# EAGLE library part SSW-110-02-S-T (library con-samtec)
THROUGH-HOLE .025" SQ POST SOCKET Source: Samtec SSW.pdf
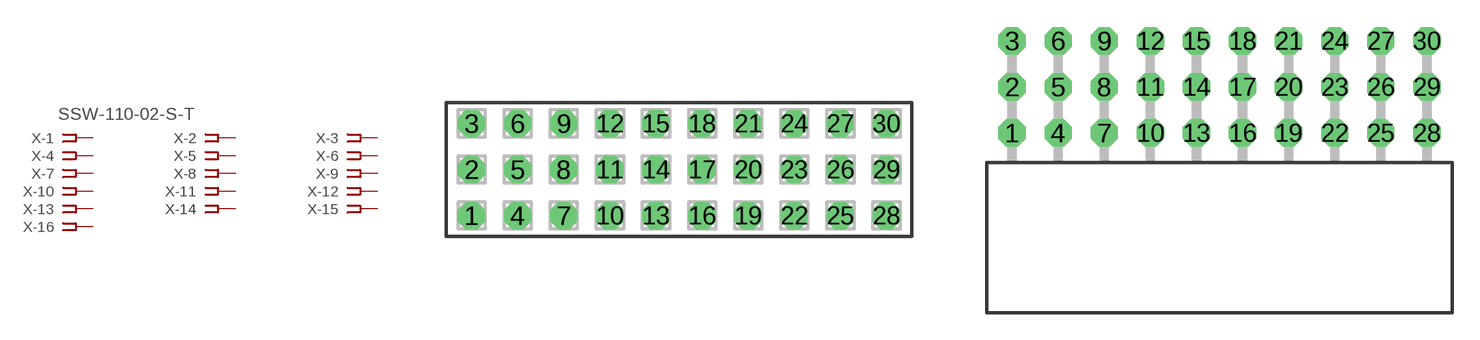
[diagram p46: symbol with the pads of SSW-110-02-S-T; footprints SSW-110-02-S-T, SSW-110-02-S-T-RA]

Designator prefix X; gates -1=FPINV -2=FPIN -3=FPIN -4=FPIN -5=FPIN -6=FPIN -7=FPIN -8=FPIN -9=FPIN -10=FPIN -11=FPIN -12=FPIN -13=FPIN -14=FPIN -15=FPIN -16=FPIN -17=FPIN -18=FPIN -19=FPIN -20=FPIN -21=FPIN -22=FPIN -23=FPIN -24=FPIN -25=FPIN -26=FPIN -27=FPIN -28=FPIN -29=FPIN -30=FPIN

## SSW-110-02-S-T (MPN: SSW-110-02-S-T; OC_FARNELL: unknown; OC_NEWARK: 82P5236)  [SSW-110-02-S-T]
1  -1:1  pas
2  -2:1  pas
3  -3:1  pas
4  -4:1  pas
5  -5:1  pas
6  -6:1  pas
7  -7:1  pas
8  -8:1  pas
9  -9:1  pas
10  -10:1  pas
11  -11:1  pas
12  -12:1  pas
13  -13:1  pas
14  -14:1  pas
15  -15:1  pas
16  -16:1  pas
17  -17:1  pas
18  -18:1  pas
19  -19:1  pas
20  -20:1  pas
21  -21:1  pas
22  -22:1  pas
23  -23:1  pas
24  -24:1  pas
25  -25:1  pas
26  -26:1  pas
27  -27:1  pas
28  -28:1  pas
29  -29:1  pas
30  -30:1  pas

## SSW-110-02-S-TRA (MPN: SSW-110-02-S-T-RA; OC_FARNELL: unknown; OC_NEWARK: 82P5237)  [SSW-110-02-S-T-RA]
Pads as for SSW-110-02-S-T

## Footprint SSW-110-02-S-T (pad centres in mm)
THROUGH-HOLE .025" SQ POST SOCKET Source: Samtec SSW.pdf
drill 1 pad 1.5 octagon: 1 -11.43,-2.54; 2 -11.43,0; 3 -11.43,2.54; 4 -8.89,-2.54; 5 -8.89,0; 6 -8.89,2.54; 7 -6.35,-2.54; 8 -6.35,0; 9 -6.35,2.54; 10 -3.81,-2.54; 11 -3.81,0; 12 -3.81,2.54; 13 -1.27,-2.54; 14 -1.27,0; 15 -1.27,2.54; 16 1.27,-2.54; 17 1.27,0; 18 1.27,2.54; 19 3.81,-2.54; 20 3.81,0; 21 3.81,2.54; 22 6.35,-2.54; 23 6.35,0; 24 6.35,2.54; 25 8.89,-2.54; 26 8.89,0; 27 8.89,2.54; 28 11.43,-2.54; 29 11.43,0; 30 11.43,2.54

## Footprint SSW-110-02-S-T-RA (pad centres in mm)
THROUGH-HOLE .025" SQ POST SOCKET Source: Samtec SSW.pdf
drill 1 pad 1.5 octagon: 1 -11.43,1.524; 2 -11.43,4.064; 3 -11.43,6.604; 4 -8.89,1.524; 5 -8.89,4.064; 6 -8.89,6.604; 7 -6.35,1.524; 8 -6.35,4.064; 9 -6.35,6.604; 10 -3.81,1.524; 11 -3.81,4.064; 12 -3.81,6.604; 13 -1.27,1.524; 14 -1.27,4.064; 15 -1.27,6.604; 16 1.27,1.524; 17 1.27,4.064; 18 1.27,6.604; 19 3.81,1.524; 20 3.81,4.064; 21 3.81,6.604; 22 6.35,1.524; 23 6.35,4.064; 24 6.35,6.604; 25 8.89,1.524; 26 8.89,4.064; 27 8.89,6.604; 28 11.43,1.524; 29 11.43,4.064; 30 11.43,6.604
